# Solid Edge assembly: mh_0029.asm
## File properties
Title: holder_handle_unit
Author: edge
Template: normal.asm
Last saved by: edge
Revision: 24
Application: Solid Edge
文書内容のタイプ: 1
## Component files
mh_0031.par
mh_0030.par
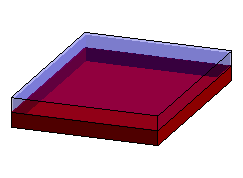
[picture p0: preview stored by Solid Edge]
